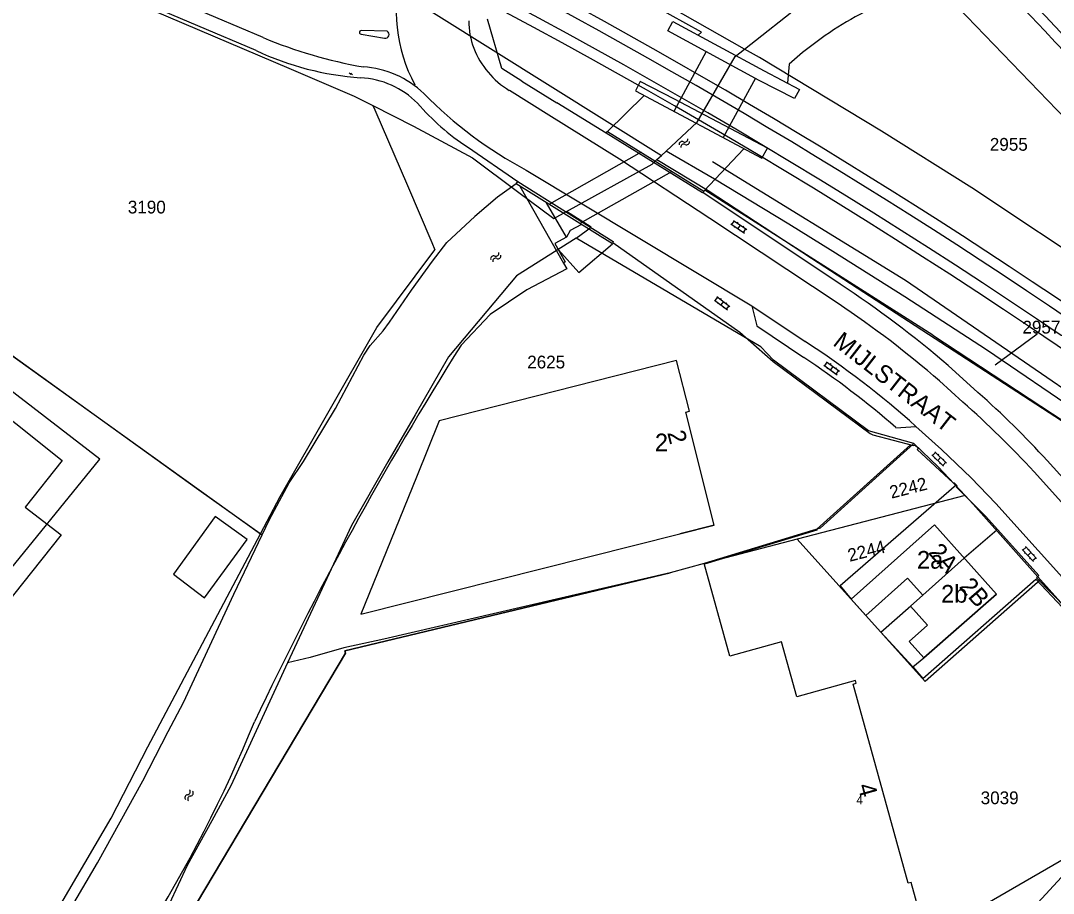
# Model space of a CAD drawing. Extents: x 148816 to 151297, y 399515 to 402500.
# Drawn here: x 149700.3 to 149846, y 399838.3 to 399961.5 of the extents above; entities that cross this region are included whole.
import ezdxf

# ---------------------------------------------------------------- set-up
doc = ezdxf.new("R2010")
doc.units = 0
for name, color, linetype in [('B01 Hoofdgebouw  [D] Norm', 7, 'Continuous'), ('B01 Hoofdgebouw  [T] Norm', 7, 'Continuous'), ('B01 hoofgebouw', 7, 'Continuous'), ('B02 Bijgebouw  [D] Norm', 7, 'Continuous'), ('G01 perceelsgrens', 7, 'Continuous'), ('G02 sectiegrens', 7, 'Continuous'), ('Q01 Spoorrail  [D] Norm', 7, 'Continuous'), ('S02 Open verharding  Norm', 7, 'Continuous'), ('S05 Water  Norm', 7, 'Continuous'), ('T01 Muur  [T] Gem', 7, 'Continuous'), ('T04 Haag heg  [D] Gem', 7, 'Continuous'), ('T09 Insteek water  [T] Norm', 7, 'Continuous'), ('V00 Kant verharding algemeen  [T] Norm', 7, 'Continuous'), ('V00 Kant verharding algemeen secundair  [T] Gem', 7, 'Continuous'), ('V06 Kant onverhard  [T] Gem', 7, 'Continuous'), ('Z01 perceelnummer', 7, 'Continuous'), ('Z02 huisnummer', 7, 'Continuous'), ('Z02 Huisnummer  [Tekst] Norm', 7, 'Continuous'), ('Z06 straatnaam', 7, 'Continuous')]:
    doc.layers.add(name, color=color, linetype=linetype)

msp = doc.modelspace()

# ---------------------------------------------------------------- linework, layer by layer
at = {"layer": 'B01 Hoofdgebouw  [D] Norm'}
for p, q in [((149711.47, 399899.6), (149698.12, 399909.89)), ((149684.88, 399866.84), (149711.47, 399899.6)), ((149796.76, 399884.9), (149812.64, 399889.72)), ((149812.64, 399889.72), (149812.64, 399889.56)), ((149812.64, 399889.56), (149796.79, 399884.8)), ((149827.6, 399880.39), (149833.45, 399885.63))]:
    msp.add_line(p, q, dxfattribs=at)
for points in [[(149781.37, 399910.6), (149759.38, 399905.01), (149756.15, 399897.04), (149748.33, 399877.72), (149793.32, 399889.06)], [(149676.84, 399731.98), (149671.64, 399750), (149668.17, 399762.76), (149668.72, 399762.79), (149714.71, 399819.36), (149746.14, 399872.21), (149746.04, 399872.57), (149791.94, 399883.57)]]:
    msp.add_lwpolyline(points, dxfattribs=at)
at = {"layer": 'B01 Hoofdgebouw  [T] Norm'}
for p, q in [((149829.24, 399890.32), (149817.51, 399879.86)), ((149837.98, 399880.57), (149829.24, 399890.32)), ((149796.76, 399884.9), (149791.94, 399883.57)), ((149800.37, 399871.8), (149796.76, 399884.9)), ((149819.57, 399877.55), (149825.45, 399882.8)), ((149825.45, 399882.8), (149827.6, 399880.39)), ((149817.51, 399879.86), (149819.57, 399877.55)), ((149827.6, 399880.39), (149825.88, 399878.86)), ((149827.74, 399871.58), (149837.98, 399880.57)), ((149825.88, 399878.86), (149828.26, 399876.18)), ((149828.26, 399876.18), (149825.68, 399873.88)), ((149807.69, 399873.81), (149800.37, 399871.8)), ((149809.81, 399866.08), (149807.69, 399873.81)), ((149825.68, 399873.88), (149827.74, 399871.58)), ((149818.09, 399868.35), (149809.81, 399866.08)), ((149817.77, 399867.85), (149818.19, 399867.99)), ((149825.56, 399839.77), (149817.77, 399867.85)), ((149818.19, 399867.99), (149818.09, 399868.35)), ((149825.97, 399839.88), (149825.56, 399839.77)), ((149827.2, 399835.47), (149825.97, 399839.88))]:
    msp.add_line(p, q, dxfattribs=at)
msp.add_lwpolyline([(149793.32, 399889.06), (149798.17, 399890.28), (149794.15, 399906.24), (149794.68, 399906.36), (149792.87, 399913.5), (149781.37, 399910.6)], dxfattribs=at)
at = {"layer": 'B01 hoofgebouw'}
for points in [[(149680.2, 399920.1), (149706.18, 399899.4), (149700.94, 399892.82), (149706.02, 399888.9), (149687.08, 399865.13), (149655.75, 399889.41)], [(149792.87, 399913.5), (149781.37, 399910.6)], [(149794.68, 399906.36), (149792.87, 399913.5)], [(149781.37, 399910.59), (149759.38, 399905.01), (149756.15, 399897.04), (149748.33, 399877.72)], [(149794.15, 399906.24), (149794.68, 399906.36)], [(149798.17, 399890.28), (149794.15, 399906.24)], [(149798.17, 399890.28), (149793.32, 399889.06)], [(149837.98, 399880.57), (149827.74, 399871.58), (149825.68, 399873.88), (149828.26, 399876.18), (149825.88, 399878.86), (149827.6, 399880.39), (149825.45, 399882.8), (149819.57, 399877.55), (149817.51, 399879.86), (149829.24, 399890.32), (149837.98, 399880.57)], [(149748.33, 399877.72), (149793.32, 399889.06)], [(149796.76, 399884.9), (149791.94, 399883.57), (149746.04, 399872.57)], [(149800.37, 399871.8), (149796.76, 399884.9)], [(149807.69, 399873.81), (149800.37, 399871.8)], [(149809.81, 399866.08), (149807.69, 399873.81)], [(149746.14, 399872.21), (149714.71, 399819.36), (149668.72, 399762.79), (149668.17, 399762.76), (149671.64, 399750), (149678.17, 399727.16), (149748.5, 399746.59)], [(149746.04, 399872.57), (149746.14, 399872.21)], [(149746.1, 399872.38), (149746.19, 399872.4)], [(149818.09, 399868.35), (149809.81, 399866.08)], [(149817.77, 399867.85), (149818.19, 399867.99)], [(149825.56, 399839.77), (149817.77, 399867.85)], [(149818.19, 399867.99), (149818.09, 399868.35)], [(149825.97, 399839.88), (149825.56, 399839.77)], [(149827.2, 399835.47), (149825.97, 399839.88)]]:
    msp.add_lwpolyline(points, dxfattribs=at)
at = {"layer": 'B02 Bijgebouw  [D] Norm'}
for p, q in [((149727.76, 399891.53), (149721.87, 399883.38)), ((149732.29, 399888.25), (149727.76, 399891.53)), ((149727.76, 399891.53), (149727.76, 399891.53)), ((149726.27, 399880.05), (149732.29, 399888.25)), ((149721.87, 399883.38), (149726.27, 399880.05))]:
    msp.add_line(p, q, dxfattribs=at)
at = {"layer": 'G01 perceelsgrens'}
for points in [[(149802.47, 399957.46), (149790.25, 399964.42), (149774.83, 399972.99), (149760.38, 399980.42), (149762.51, 399985.17)], [(149678.53, 399971.35), (149685.79, 399971.6), (149694.54, 399970.72), (149703.15, 399968.98), (149712.62, 399965.67), (149738.18, 399954.78), (149747.36, 399950.83), (149750.02, 399949.48)], [(149824.93, 399971.33), (149852.88, 399942.28), (149864.82, 399929.5), (149871.97, 399921.82), (149900.74, 399890.71), (149870.33, 399913.56), (149853.48, 399925.26), (149834.51, 399937.87), (149821.78, 399945.87), (149804.58, 399956.25), (149802.47, 399957.46)], [(149751.17, 399967.18), (149751.29, 399967.19), (149790.74, 399942.46)], [(149656.45, 399946.07), (149680.04, 399927.84), (149734.15, 399889.05)], [(149875.76, 399887.3), (149872.21, 399889.99), (149866.85, 399893.94), (149859.28, 399899.32), (149850, 399905.88), (149836.58, 399915.04), (149825.09, 399922.51), (149814.91, 399928.89), (149808.68, 399932.76), (149798.2, 399939.12), (149791.4, 399943.07)], [(149790.08, 399941.85), (149797.33, 399937.51), (149811.91, 399927.96), (149828.42, 399917.25), (149849.83, 399903.3), (149871.51, 399889.28), (149875.76, 399887.3)], [(149778.71, 399930.79), (149780.8, 399932.34), (149777.31, 399934.53)], [(149778.71, 399930.79), (149770.28, 399925.44), (149760.68, 399914.03), (149755.99, 399905.87), (149752.14, 399899.2), (149747.01, 399890.25), (149743.52, 399882.77), (149737.99, 399870.84)], [(149826.33, 399901.82), (149819.96, 399903.61), (149806.56, 399913.57), (149804.73, 399915.44), (149778.71, 399930.79)], [(149826.33, 399901.82), (149813.1, 399889.84), (149796.76, 399884.9)], [(149833.59, 399894.45), (149829.77, 399898.52), (149826.33, 399901.82)], [(149833.59, 399894.45), (149809.87, 399888.3)], [(149844.2, 399882.59), (149834.72, 399893.25), (149833.59, 399894.45)], [(149809.87, 399888.3), (149796.76, 399884.9)], [(149844.2, 399882.59), (149827.94, 399868.25), (149809.87, 399888.3)], [(149796.76, 399884.9), (149791.94, 399883.57), (149751.54, 399874.21), (149745.94, 399872.96), (149741.17, 399871.63), (149737.99, 399870.84)], [(149868.62, 399855.39), (149848.28, 399877.99), (149844.2, 399882.59)], [(149737.99, 399870.84), (149729.96, 399853.53), (149727.28, 399848.59), (149723.82, 399842.27), (149720.01, 399834.09), (149715.31, 399824.15), (149713.23, 399820.9), (149710.52, 399818.33), (149705.52, 399812.8), (149694.95, 399800.91), (149688.1, 399793.16)], [(149868.62, 399855.39), (149834.91, 399835.86), (149834.29, 399833.18)]]:
    msp.add_lwpolyline(points, dxfattribs=at)
at = {"layer": 'G02 sectiegrens'}
for points in [[(149802.47, 399957.46), (149810.68, 399963.91), (149816.82, 399966.87)], [(149791.4, 399943.07), (149795.78, 399947.13), (149801.11, 399956.39), (149802.47, 399957.46)], [(149750.02, 399949.48), (149755.74, 399946.57), (149764.05, 399942.12), (149770.44, 399937.36)], [(149750.02, 399949.48), (149750.28, 399948.87), (149754.9, 399938.2), (149758.33, 399930.14), (149758.75, 399929.14)], [(149790.08, 399941.85), (149790.74, 399942.46)], [(149790.74, 399942.46), (149791.4, 399943.07)], [(149777.31, 399934.53), (149789.41, 399941.23), (149790.08, 399941.85)], [(149770.44, 399937.36), (149775.55, 399933.55), (149777.31, 399934.53)], [(149734.15, 399889.05), (149736.93, 399894.33), (149750.57, 399918.16), (149758.75, 399929.14)], [(149685.52, 399809.42), (149697.07, 399823.5), (149702.27, 399830.48), (149713.1, 399848.95), (149718.28, 399858.99), (149734.15, 399889.05)]]:
    msp.add_lwpolyline(points, dxfattribs=at)
at = {"layer": 'Q01 Spoorrail  [D] Norm'}
for points in [[(149845.9, 399961.04), (149841.97, 399965.2), (149838.03, 399969.37)], [(149844.81, 399960.01), (149840.88, 399964.17), (149836.94, 399968.34)]]:
    msp.add_lwpolyline(points, dxfattribs=at)
for centre, radius, start, end in [((149374.9, 399222.57), 839.82, 47.97661, 67.90149), ((149374.91, 399222.59), 843.8, 50.16342, 67.24111), ((149374.9, 399222.57), 838.32, 47.97661, 67.90149), ((149374.91, 399222.59), 842.3, 50.16342, 67.24111), ((146203.87, 396528.63), 5003.08, 43.17147, 43.3027), ((146203.87, 396528.63), 5004.58, 43.17147, 43.3027)]:
    msp.add_arc(centre, radius, start, end, dxfattribs=at)
at = {"layer": 'S02 Open verharding  Norm'}
for p, q in [((149800.54, 399932.78), (149802.44, 399931.49)), ((149800.66, 399932.69), (149801, 399933.19)), ((149800.88, 399933.27), (149802.78, 399931.98)), ((149801.08, 399932.41), (149800.99, 399932.29)), ((149801.5, 399933.03), (149801.41, 399932.91)), ((149801.83, 399932.63), (149801.49, 399932.13)), ((149802.32, 399932.47), (149802.24, 399932.35)), ((149802.32, 399931.57), (149802.65, 399932.07)), ((149801.9, 399931.85), (149801.82, 399931.73)), ((149798.2, 399922.05), (149800.04, 399920.67)), ((149798.32, 399921.96), (149798.68, 399922.44)), ((149798.56, 399922.53), (149800.4, 399921.15)), ((149799.17, 399922.26), (149799.08, 399922.14)), ((149799.48, 399921.84), (149799.12, 399921.36)), ((149798.72, 399921.66), (149798.63, 399921.54)), ((149799.52, 399921.06), (149799.43, 399920.94)), ((149799.97, 399921.66), (149799.88, 399921.54)), ((149799.92, 399920.76), (149800.28, 399921.24)), ((149813.77, 399912.78), (149814.12, 399913.26)), ((149814, 399913.35), (149815.85, 399911.99)), ((149814.61, 399913.09), (149814.53, 399912.97)), ((149813.65, 399912.87), (149815.5, 399911.5)), ((149814.17, 399912.48), (149814.08, 399912.36)), ((149814.93, 399912.67), (149814.57, 399912.19)), ((149814.97, 399911.89), (149814.89, 399911.77)), ((149815.42, 399912.49), (149815.33, 399912.37)), ((149815.38, 399911.59), (149815.73, 399912.08)), ((149828.88, 399900.22), (149830.53, 399898.62)), ((149828.99, 399900.12), (149829.41, 399900.55)), ((149829.3, 399900.65), (149830.95, 399899.04)), ((149829.87, 399900.3), (149829.77, 399900.2)), ((149829.35, 399899.77), (149829.24, 399899.66)), ((149830.12, 399899.85), (149829.71, 399899.42)), ((149830.06, 399899.07), (149829.96, 399898.96)), ((149830.42, 399898.72), (149830.84, 399899.15)), ((149830.59, 399899.61), (149830.48, 399899.5)), ((149841.64, 399886.86), (149843.2, 399885.17)), ((149841.74, 399886.75), (149842.19, 399887.16)), ((149842.08, 399887.27), (149843.64, 399885.57)), ((149842.63, 399886.89), (149842.52, 399886.79)), ((149842.08, 399886.38), (149841.97, 399886.28)), ((149842.86, 399886.42), (149842.42, 399886.02)), ((149842.76, 399885.65), (149842.65, 399885.55)), ((149843.1, 399885.28), (149843.54, 399885.68)), ((149843.31, 399886.15), (149843.2, 399886.05))]:
    msp.add_line(p, q, dxfattribs=at)
at = {"layer": 'S05 Water  Norm'}
for p, q in [((149746.66, 399954.09), (149746.89, 399953.86)), ((149746.89, 399953.86), (149746.92, 399954.04)), ((149746.92, 399954.04), (149747.15, 399953.8))]:
    msp.add_line(p, q, dxfattribs=at)
for centre, start, end in [((149793.64, 399943.99), 62.977, 186.832), ((149793.9, 399943.62), 62.977, 186.832), ((149794.03, 399944.75), 242.977, 6.832), ((149794.28, 399944.38), 242.977, 6.832), ((149767.05, 399927.86), 68.0028, 191.8578), ((149767.34, 399927.51), 68.0028, 191.8578), ((149767.37, 399928.65), 248.0028, 11.8578), ((149767.66, 399928.3), 248.0028, 11.8578), ((149723.9, 399851.83), 94.9222, 218.7772), ((149723.83, 399852.68), 274.9222, 38.7772), ((149724.32, 399851.65), 94.9222, 218.7772), ((149724.25, 399852.5), 274.9222, 38.7772)]:
    msp.add_arc(centre, 0.425, start, end, dxfattribs=at)
at = {"layer": 'T01 Muur  [T] Gem'}
msp.add_lwpolyline([(149897.41, 399867.09), (149888.11, 399880.2), (149868.18, 399895.28), (149825.16, 399924.79), (149797.93, 399941.55)], dxfattribs=at)
at = {"layer": 'T04 Haag heg  [D] Gem'}
for p, q in [((149829.04, 399917.1), (149796.83, 399937.54)), ((149776.19, 399929.11), (149779.07, 399925.91)), ((149779.07, 399925.91), (149783.82, 399929.97)), ((149684.49, 399924.75), (149708.36, 399907.61)), ((149829.04, 399917.1), (149855.29, 399899.78)), ((149708.36, 399907.61), (149725.47, 399895.29)), ((149825.88, 399901.62), (149812.64, 399889.72)), ((149832.35, 399895.97), (149815.93, 399881.74)), ((149725.47, 399895.29), (149734.39, 399888.93)), ((149838.05, 399889.6), (149833.45, 399885.63)), ((149815.93, 399881.74), (149817.51, 399879.86)), ((149821.67, 399875.17), (149825.91, 399878.92)), ((149819.57, 399877.55), (149821.67, 399875.17)), ((149821.67, 399875.17), (149826.22, 399870.3)), ((149826.22, 399870.3), (149827.74, 399871.58)), ((149826.22, 399870.3), (149827.62, 399868.66))]:
    msp.add_line(p, q, dxfattribs=at)
for points in [[(149827.62, 399868.66), (149843.54, 399882.66), (149854.03, 399871.54), (149853.63, 399871.12), (149860.86, 399863.27)], [(149864.74, 399859.73), (149803.69, 399793.42), (149777.29, 399760.87), (149765.82, 399770.29), (149758.6, 399796.33), (149754.39, 399811.51)]]:
    msp.add_lwpolyline(points, dxfattribs=at)
at = {"layer": 'T09 Insteek water  [T] Norm'}
for p, q in [((149796.36, 399959.83), (149786.71, 399965.2)), ((149795.92, 399959.4), (149796.36, 399959.83)), ((149812.68, 399958.52), (149810.64, 399956.95)), ((149810.64, 399956.95), (149808.76, 399955.32)), ((149808.76, 399955.32), (149808.5, 399952.7)), ((149788.26, 399950.87), (149783.12, 399945.81)), ((149796.72, 399937.42), (149802.37, 399943.37)), ((149770.25, 399938.42), (149767.59, 399936.55)), ((149770.75, 399938.12), (149776.93, 399927.25)), ((149767.59, 399936.55), (149764.39, 399933.83)), ((149764.39, 399933.83), (149760.43, 399930.14)), ((149758.44, 399927.51), (149760.43, 399930.14)), ((149755.47, 399923.42), (149758.44, 399927.51)), ((149777.37, 399926.45), (149771.73, 399923.49)), ((149776.93, 399927.25), (149777.37, 399926.45)), ((149752.35, 399918.94), (149755.47, 399923.42)), ((149771.73, 399923.49), (149766.55, 399920.02)), ((149751.46, 399917.72), (149752.35, 399918.94)), ((149766.55, 399920.02), (149762.46, 399915.68)), ((149749.63, 399915.65), (149751.46, 399917.72)), ((149748.74, 399914.25), (149749.63, 399915.65)), ((149744.73, 399906.75), (149748.74, 399914.25)), ((149740.23, 399899.27), (149744.73, 399906.75)), ((149738.2, 399896.24), (149740.23, 399899.27)), ((149735.41, 399891.07), (149738.2, 399896.24)), ((149734.39, 399888.94), (149735.41, 399891.07)), ((149730.41, 399880.57), (149734.39, 399888.94)), ((149723.3, 399865.25), (149730.41, 399880.57)), ((149721.15, 399861.18), (149723.3, 399865.25)), ((149717.54, 399854.23), (149721.15, 399861.18)), ((149711.14, 399842.66), (149717.54, 399854.23)), ((149707.49, 399836.4), (149711.14, 399842.66))]:
    msp.add_line(p, q, dxfattribs=at)
for centre, radius, start, end in [((149843.07, 399917.25), 51.25, 113.5925, 126.3707), ((150183.95, 399649.87), 498.3, 147.7626, 154.7377), ((149548.23, 399938.46), 200.04, 318.2664, 337.6939)]:
    msp.add_arc(centre, radius, start, end, dxfattribs=at)
at = {"layer": 'V00 Kant verharding algemeen  [T] Norm'}
for p, q in [((149734.53, 399959.08), (149717.55, 399966.29)), ((149733.55, 399957.25), (149717.11, 399964.2)), ((149768.23, 399954.71), (149766.2, 399961.69)), ((149791.64, 399960.01), (149792.34, 399961.32)), ((149792.34, 399961.32), (149805.24, 399954.4)), ((149804.53, 399953.04), (149791.64, 399960.01)), ((149771.04, 399952.93), (149768.23, 399954.71)), ((149805.24, 399954.4), (149810.2, 399951.76)), ((149771.04, 399952.93), (149775.96, 399949.85)), ((149787.72, 399952.88), (149787.06, 399951.54)), ((149792.55, 399950.39), (149787.72, 399952.88)), ((149809.49, 399950.47), (149804.53, 399953.04)), ((149774.86, 399948.11), (149769.27, 399951.62)), ((149787.06, 399951.54), (149804.91, 399942.06)), ((149810.2, 399951.76), (149809.49, 399950.47)), ((149782.95, 399945.57), (149775.96, 399949.85)), ((149805.71, 399943.47), (149792.55, 399950.39)), ((149782.95, 399945.57), (149783.12, 399945.81)), ((149796.5, 399937.17), (149782.95, 399945.57)), ((149783.12, 399945.81), (149796.72, 399937.42)), ((149763.35, 399943.64), (149770.45, 399938.77)), ((149804.91, 399942.06), (149805.71, 399943.47)), ((149770.25, 399938.42), (149770.45, 399938.77)), ((149783.8, 399929.98), (149770.25, 399938.42)), ((149770.45, 399938.77), (149783.92, 399930.29)), ((149796.72, 399937.42), (149796.5, 399937.17)), ((149777.33, 399930.93), (149774.53, 399935.77)), ((149779.45, 399932.72), (149777.86, 399931.87)), ((149777.33, 399930.93), (149775.68, 399930.01)), ((149777.86, 399931.87), (149777.33, 399930.93)), ((149775.68, 399930.01), (149777.15, 399927.42)), ((149783.92, 399930.29), (149783.8, 399929.98)), ((149777.15, 399927.42), (149776.93, 399927.25))]:
    msp.add_line(p, q, dxfattribs=at)
for points in [[(149815.64, 399921.54), (149797.56, 399933.56), (149784.82, 399941.94), (149774.86, 399948.11)], [(149771.64, 399940.39), (149803.47, 399921.21), (149804.19, 399918.41), (149810.8, 399913.94)], [(149815.96, 399924.28), (149796.55, 399937.23)], [(149783.87, 399930.15), (149801.81, 399917.51), (149806.49, 399913.38), (149820.18, 399903.21), (149820.54, 399903.04), (149826.3, 399901.51), (149826.5, 399901.56), (149826.95, 399901.13), (149826.79, 399900.97), (149831.87, 399896.28), (149832.04, 399896.28), (149832.47, 399895.84), (149832.33, 399895.7), (149836.5, 399891.52), (149843.98, 399883.18), (149843.65, 399882.86), (149850, 399876.35), (149860.84, 399864.31), (149870.12, 399853.99)], [(149803.47, 399921.21), (149811.02, 399916.18)], [(149835.39, 399909.01), (149831.18, 399912.81)], [(149833.27, 399907.64), (149829.96, 399910.63)], [(149823.8, 399904.04), (149826.62, 399904.22), (149830.24, 399900.94), (149834.44, 399896.96)], [(149854.13, 399889.47), (149845.15, 399899.4)], [(149883.79, 399852.87), (149843.3, 399897.83)], [(149834.44, 399896.96), (149837.9, 399893.35)], [(149837.9, 399893.35), (149868.21, 399859.74)]]:
    msp.add_lwpolyline(points, dxfattribs=at)
for centre, radius, start, end in [((149775.32, 399962.89), 22.03, 164.2287, 208.3745), ((149774.57, 399961.49), 11.04, 180.1697, 221.3224), ((149760.24, 400020.6), 66.68, 247.3172, 259.9785), ((149751.08, 399994.34), 41.03, 244.7, 266.0962), ((149747.75, 399941.29), 13.68, 46.2421, 86.2679), ((149775.62, 399962.04), 12.21, 219.9778, 238.6312), ((149747.57, 399941.05), 12.38, 45.1019, 86.6686), ((149799.76, 399993.07), 59.72, 224.5643, 241.9122), ((149782.42, 399972.46), 34.56, 220.932, 236.512), ((149734.22, 399799.99), 148.76, 49.3234, 56.6699), ((149738.83, 399806), 138.75, 48.945, 56.3832), ((149741.27, 399809.06), 127.83, 48.1092, 56.9278), ((149742.54, 399810.79), 123.7, 48.9299, 56.5041), ((149746.64, 399809.24), 133.53, 42.4656, 48.345), ((149736.28, 399798.45), 146.05, 42.8785, 48.3861)]:
    msp.add_arc(centre, radius, start, end, dxfattribs=at)
at = {"layer": 'V00 Kant verharding algemeen secundair  [T] Gem'}
for p, q in [((149752.04, 399959.98), (149748.41, 399960.05)), ((149748.36, 399959.54), (149751.67, 399958.97))]:
    msp.add_line(p, q, dxfattribs=at)
for centre, radius, start, end in [((149748.36, 399959.8), 0.257, 79.185, 269.8175), ((149751.76, 399959.51), 0.548, 260.1594, 59.9234)]:
    msp.add_arc(centre, radius, start, end, dxfattribs=at)
at = {"layer": 'V06 Kant onverhard  [T] Gem'}
for p, q in [((149792.53, 399948.7), (149797.1, 399957.16)), ((149799.48, 399945.01), (149804.06, 399953.38)), ((149787.85, 399942.89), (149774.92, 399935.55)), ((149779.24, 399932.88), (149792.2, 399940.19))]:
    msp.add_line(p, q, dxfattribs=at)
at = {"layer": 'Z01 perceelnummer'}
msp.add_lwpolyline([(149843.73, 399917.22), (149837.79, 399912.84)], dxfattribs=at)

# ---------------------------------------------------------------- texts
for s, p in [('2955', (149837.06, 399943.11)), ('3190', (149715.44, 399934.26)), ('2957', (149841.66, 399917.32)), ('2625', (149771.79, 399912.4)), ('3039', (149835.77, 399850.92))]:
    msp.add_text(s, height=1.8, dxfattribs=at).set_placement(p)
for s, rotation, p in [('2242', 14.3714, (149823.18, 399894.01)), ('2244', 14.4415, (149817.28, 399885.11))]:
    msp.add_text(s, height=1.8, rotation=rotation, dxfattribs=at).set_placement(p)
at = {"layer": 'Z02 huisnummer'}
for s, rotation, p in [('2', 284.1196, (149791.53, 399903.34)), ('2A', 311.3529, (149828.26, 399886.38)), ('2B', 311.0674, (149832.64, 399881.56)), ('4', 285.4812, (149818.37, 399853.52))]:
    msp.add_text(s, height=2.5, rotation=rotation, dxfattribs=at).set_placement(p)
at = {"layer": 'Z02 Huisnummer  [Tekst] Norm'}
for s, height, p in [('2', 2.5, (149789.8, 399900.7)), ('2a', 2.498, (149826.78, 399884.15)), ('2b', 2.498, (149830.18, 399879.35)), ('4', 1.25, (149818.23, 399850.9))]:
    msp.add_text(s, height=height, dxfattribs=at).set_placement(p)
at = {"layer": 'Z06 straatnaam'}
msp.add_text('MIJLSTRAAT', height=2.5, rotation=322.1099, dxfattribs=at).set_placement((149814.78, 399915.77))

doc.saveas('drawing.dxf')
